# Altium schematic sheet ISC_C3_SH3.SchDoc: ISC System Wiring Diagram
size B; DrawnBy: Filiberto Clara; Engineer: Filiberto Clara; Organization: LIGO Laboratory; Address1: California Institute of Technology; Address2: Massachusetts Institute of Technology; SheetNumber: 7; SheetTotal: 39
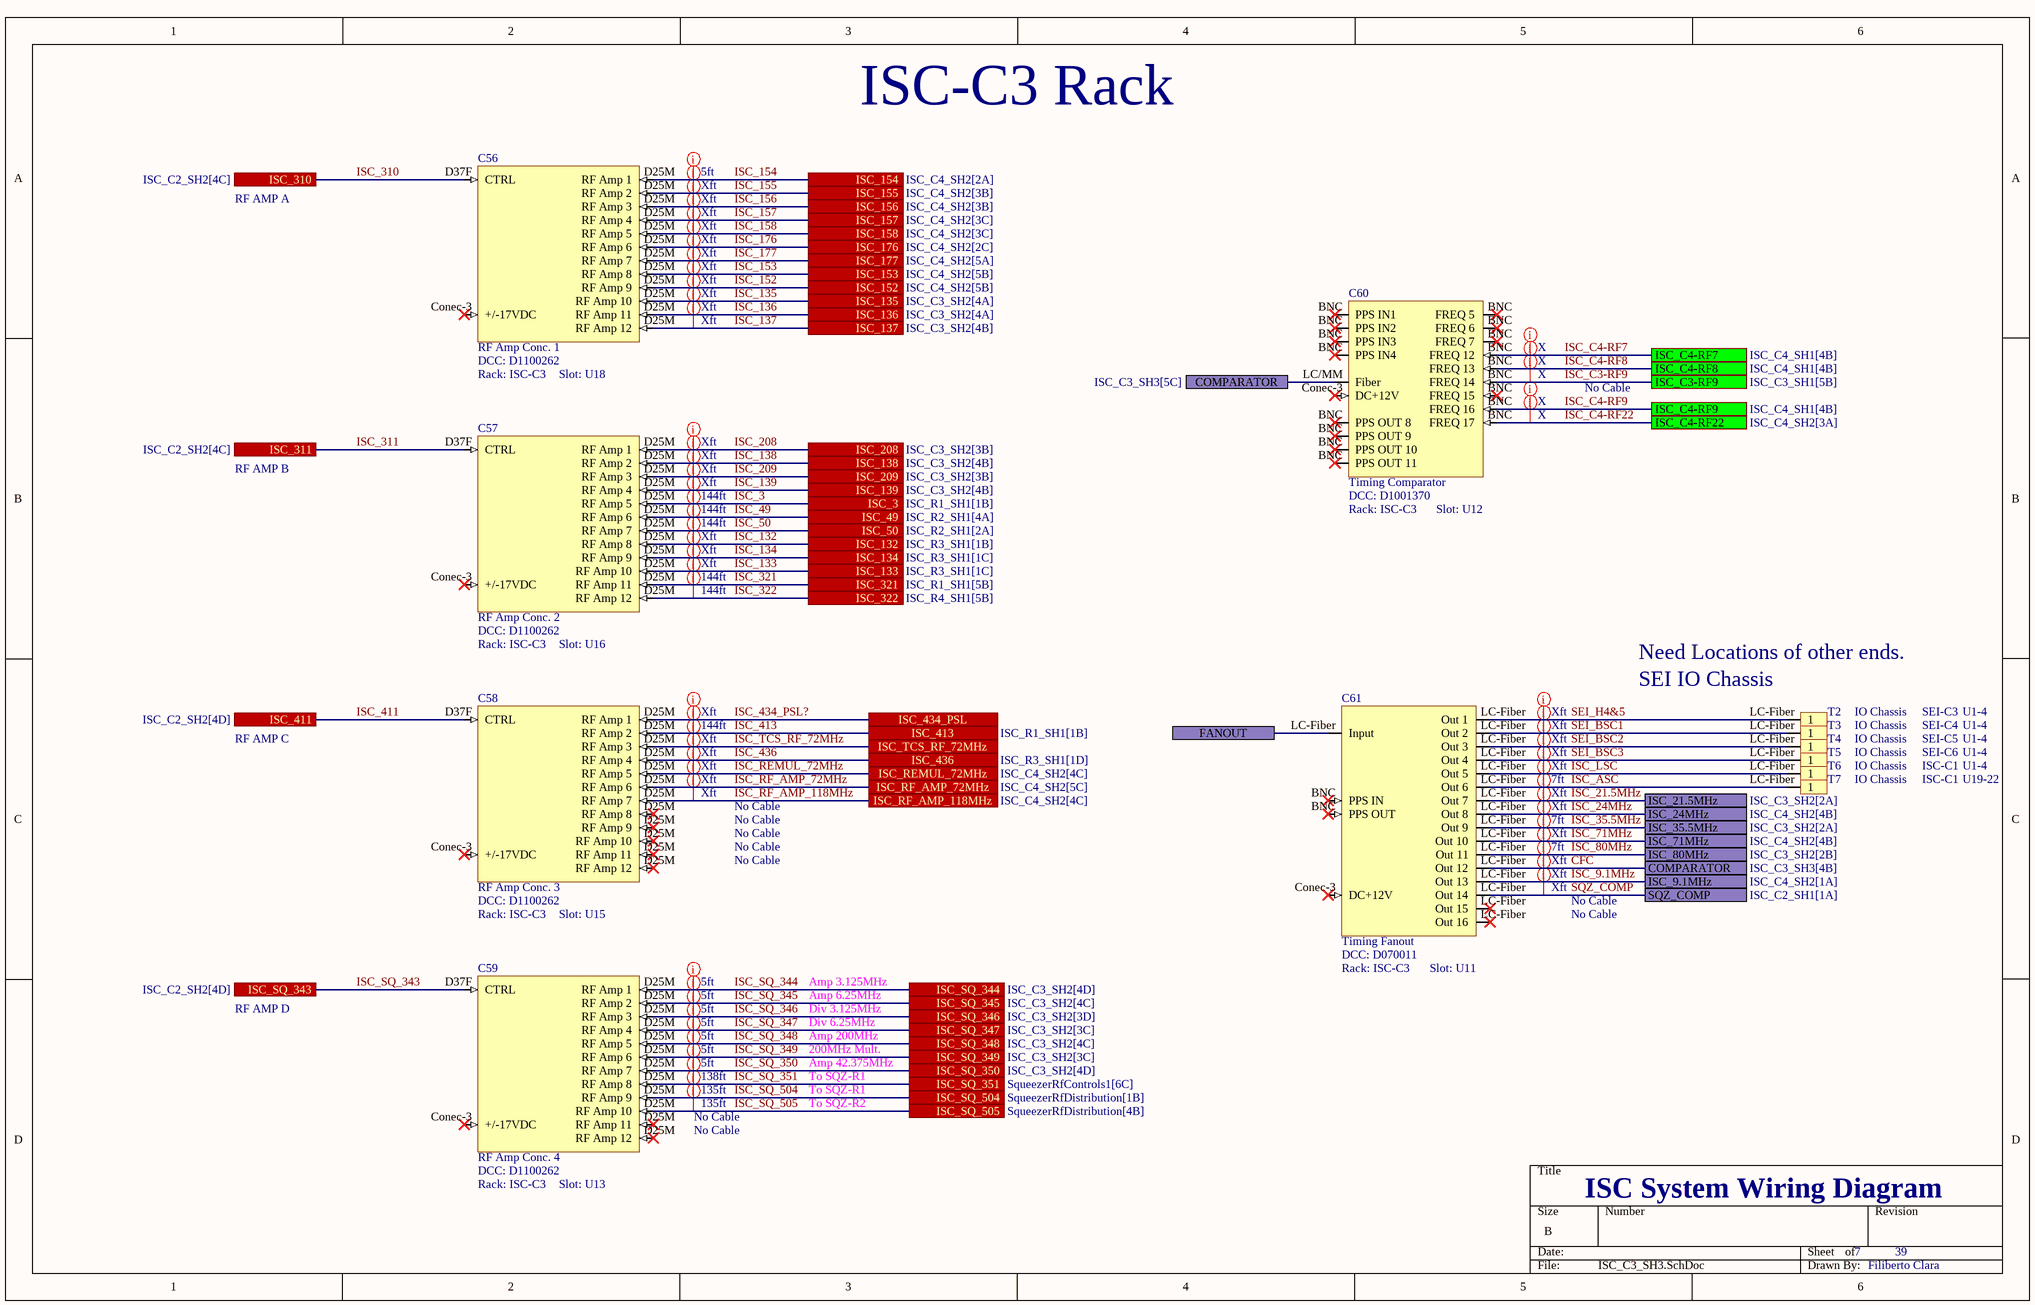
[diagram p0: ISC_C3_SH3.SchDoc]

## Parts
C56  RF Amp Conc. 1  DCC: D1100262  Rack: ISC-C3  Slot: U18
C57  RF Amp Conc. 2  DCC: D1100262  Rack: ISC-C3  Slot: U16
C58  RF Amp Conc. 3  DCC: D1100262  Rack: ISC-C3  Slot: U15
C59  RF Amp Conc. 4  DCC: D1100262  Rack: ISC-C3  Slot: U13
C60  Timing Comparator  DCC: D1001370  Rack: ISC-C3  Slot: U12
C61  Timing Fanout  DCC: D070011  Rack: ISC-C3  Slot: U11
T2  IO Chassis  Rack: SEI-C3  Slot: U1-4
T3  IO Chassis  Rack: SEI-C4  Slot: U1-4
T4  IO Chassis  Rack: SEI-C5  Slot: U1-4
T5  IO Chassis  Rack: SEI-C6  Slot: U1-4
T6  IO Chassis  Rack: ISC-C1  Slot: U1-4
T7  IO Chassis  Rack: ISC-C1  Slot: U19-22

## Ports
COMPARATOR (see ISC_C3_SH3[4B]), COMPARATOR (see ISC_C3_SH3[5C]), FANOUT, ISC_3 (see ISC_R1_SH1[1B]), ISC_9.1MHz (see ISC_C4_SH2[1A]), ISC_21.5MHz (see ISC_C3_SH2[2A]), ISC_24MHz (see ISC_C4_SH2[4B]), ISC_35.5MHz (see ISC_C3_SH2[2A]), ISC_49 (see ISC_R2_SH1[4A]), ISC_50 (see ISC_R2_SH1[2A]), ISC_71MHz (see ISC_C4_SH2[4B]), ISC_80MHz (see ISC_C3_SH2[2B]), ISC_132 (see ISC_R3_SH1[1B]), ISC_133 (see ISC_R3_SH1[1C]), ISC_134 (see ISC_R3_SH1[1C]), ISC_135 (see ISC_C3_SH2[4A]), ISC_136 (see ISC_C3_SH2[4A]), ISC_137 (see ISC_C3_SH2[4B]), ISC_138 (see ISC_C3_SH2[4B]), ISC_139 (see ISC_C3_SH2[4B]), ISC_152 (see ISC_C4_SH2[5B]), ISC_153 (see ISC_C4_SH2[5B]), ISC_154 (see ISC_C4_SH2[2A]), ISC_155 (see ISC_C4_SH2[3B]), ISC_156 (see ISC_C4_SH2[3B]), ISC_157 (see ISC_C4_SH2[3C]), ISC_158 (see ISC_C4_SH2[3C]), ISC_176 (see ISC_C4_SH2[2C]), ISC_177 (see ISC_C4_SH2[5A]), ISC_208 (see ISC_C3_SH2[3B]), ISC_209 (see ISC_C3_SH2[3B]), ISC_310 (see ISC_C2_SH2[4C]), ISC_311 (see ISC_C2_SH2[4C]), ISC_321 (see ISC_R1_SH1[5B]), ISC_322 (see ISC_R4_SH1[5B]), ISC_411 (see ISC_C2_SH2[4D]), ISC_413 (see ISC_R1_SH1[1B]), ISC_434_PSL, ISC_436 (see ISC_R3_SH1[1D]), ISC_C3-RF9 (see ISC_C3_SH1[5B]), ISC_C4-RF7 (see ISC_C4_SH1[4B]), ISC_C4-RF8 (see ISC_C4_SH1[4B]), ISC_C4-RF9 (see ISC_C4_SH1[4B]), ISC_C4-RF22 (see ISC_C4_SH2[3A]), ISC_REMUL_72MHz (see ISC_C4_SH2[4C]), ISC_RF_AMP_72MHz (see ISC_C4_SH2[5C]), ISC_RF_AMP_118MHz (see ISC_C4_SH2[4C]), ISC_SQ_343 (see ISC_C2_SH2[4D]), ISC_SQ_344 (see ISC_C3_SH2[4D]), ISC_SQ_345 (see ISC_C3_SH2[4C]), ISC_SQ_346 (see ISC_C3_SH2[3D]), ISC_SQ_347 (see ISC_C3_SH2[3C]), ISC_SQ_348 (see ISC_C3_SH2[4C]), ISC_SQ_349 (see ISC_C3_SH2[3C]), ISC_SQ_350 (see ISC_C3_SH2[4D]), ISC_SQ_351 (see SqueezerRfControls1[6C]), ISC_SQ_504 (see SqueezerRfDistribution[1B]), ISC_SQ_505 (see SqueezerRfDistribution[4B]), ISC_TCS_RF_72MHz, SQZ_COMP (see ISC_C2_SH1[1A])

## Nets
CFC: C60.LC/MM(Fiber) C61.LC-Fiber(Out_12) ; port COMPARATOR
FANOUT: C61.LC-Fiber(Input) ; port FANOUT
ISC_3: C57.D25M(RF_Amp_5) ; port ISC_3
ISC_9.1MHz: C61.LC-Fiber(Out_13) ; port ISC_9.1MHz
ISC_21.5MHz: C61.LC-Fiber(Out_7) ; port ISC_21.5MHz
ISC_24MHz: C61.LC-Fiber(Out_8) ; port ISC_24MHz
ISC_35.5MHz: C61.LC-Fiber(Out_9) ; port ISC_35.5MHz
ISC_49: C57.D25M(RF_Amp_6) ; port ISC_49
ISC_50: C57.D25M(RF_Amp_7) ; port ISC_50
ISC_71MHz: C61.LC-Fiber(Out_10) ; port ISC_71MHz
ISC_80MHz: C61.LC-Fiber(Out_11) ; port ISC_80MHz
ISC_132: C57.D25M(RF_Amp_8) ; port ISC_132
ISC_133: C57.D25M(RF_Amp_10) ; port ISC_133
ISC_134: C57.D25M(RF_Amp_9) ; port ISC_134
ISC_135: C56.D25M(RF_Amp_10) ; port ISC_135
ISC_136: C56.D25M(RF_Amp_11) ; port ISC_136
ISC_137: C56.D25M(RF_Amp_12) ; port ISC_137
ISC_138: C57.D25M(RF_Amp_2) ; port ISC_138
ISC_139: C57.D25M(RF_Amp_4) ; port ISC_139
ISC_152: C56.D25M(RF_Amp_9) ; port ISC_152
ISC_153: C56.D25M(RF_Amp_8) ; port ISC_153
ISC_154: C56.D25M(RF_Amp_1) ; port ISC_154
ISC_155: C56.D25M(RF_Amp_2) ; port ISC_155
ISC_156: C56.D25M(RF_Amp_3) ; port ISC_156
ISC_157: C56.D25M(RF_Amp_4) ; port ISC_157
ISC_158: C56.D25M(RF_Amp_5) ; port ISC_158
ISC_176: C56.D25M(RF_Amp_6) ; port ISC_176
ISC_177: C56.D25M(RF_Amp_7) ; port ISC_177
ISC_208: C57.D25M(RF_Amp_1) ; port ISC_208
ISC_209: C57.D25M(RF_Amp_3) ; port ISC_209
ISC_310: C56.D37F(CTRL) ; port ISC_310
ISC_311: C57.D37F(CTRL) ; port ISC_311
ISC_321: C57.D25M(RF_Amp_11) ; port ISC_321
ISC_322: C57.D25M(RF_Amp_12) ; port ISC_322
ISC_411: C58.D37F(CTRL) ; port ISC_411
ISC_413: C58.D25M(RF_Amp_2) ; port ISC_413
ISC_434_PSL?: C58.D25M(RF_Amp_1) ; port ISC_434_PSL
ISC_436: C58.D25M(RF_Amp_4) ; port ISC_436
ISC_ASC: C61.LC-Fiber(Out_6) T7.LC-Fiber(1)
ISC_C3-RF9: C60.BNC(FREQ_14) ; port ISC_C3-RF9
ISC_C4-RF7: C60.BNC(PPS_IN1) ; port ISC_C4-RF7
ISC_C4-RF8: C60.BNC(FREQ_13) ; port ISC_C4-RF8
ISC_C4-RF9: C60.BNC(FREQ_16) ; port ISC_C4-RF9
ISC_C4-RF22: C60.BNC(FREQ_17) ; port ISC_C4-RF22
ISC_LSC: C61.LC-Fiber(Out_5) T6.LC-Fiber(1)
ISC_REMUL_72MHz: C58.D25M(RF_Amp_5) ; port ISC_REMUL_72MHz
ISC_RF_AMP_72MHz: C58.D25M(RF_Amp_6) ; port ISC_RF_AMP_72MHz
ISC_RF_AMP_118MHz: C58.D25M(RF_Amp_7) ; port ISC_RF_AMP_118MHz
ISC_SQ_343: C59.D37F(CTRL) ; port ISC_SQ_343
ISC_SQ_344: C59.D25M(RF_Amp_1) ; port ISC_SQ_344
ISC_SQ_345: C59.D25M(RF_Amp_2) ; port ISC_SQ_345
ISC_SQ_346: C59.D25M(RF_Amp_3) ; port ISC_SQ_346
ISC_SQ_347: C59.D25M(RF_Amp_4) ; port ISC_SQ_347
ISC_SQ_348: C59.D25M(RF_Amp_5) ; port ISC_SQ_348
ISC_SQ_349: C59.D25M(RF_Amp_6) ; port ISC_SQ_349
ISC_SQ_350: C59.D25M(RF_Amp_7) ; port ISC_SQ_350
ISC_SQ_351: C59.D25M(RF_Amp_8) ; port ISC_SQ_351
ISC_SQ_504: C59.D25M(RF_Amp_9) ; port ISC_SQ_504
ISC_SQ_505: C59.D25M(RF_Amp_10) ; port ISC_SQ_505
ISC_TCS_RF_72MHz: C58.D25M(RF_Amp_3) ; port ISC_TCS_RF_72MHz
SEI_BSC1: C61.LC-Fiber(Out_2) T3.LC-Fiber(1)
SEI_BSC2: C61.LC-Fiber(Out_3) T4.LC-Fiber(1)
SEI_BSC3: C61.LC-Fiber(Out_4) T5.LC-Fiber(1)
SEI_H4&5: C61.LC-Fiber(Out_1) T2.LC-Fiber(1)
SQZ_COMP: C61.LC-Fiber(Out_14) ; port SQZ_COMP

Not connected (* = marked no-connect by the designer): C56 Conec-3(+/-17VDC)*; C57 Conec-3(+/-17VDC)*; C58 Conec-3(+/-17VDC)*; C59 Conec-3(+/-17VDC)*; C60 Conec-3(DC+12V)*; C61 BNC(PPS_IN)* Conec-3(DC+12V)*

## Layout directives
Length: 5ft: ISC_154, ISC_SQ_344, ISC_SQ_345, ISC_SQ_346, ISC_SQ_347, ISC_SQ_348, ISC_SQ_349, ISC_SQ_350
Length: 138ft: ISC_SQ_351
Length: Xft: CFC, ISC_9.1MHz, ISC_21.5MHz, ISC_24MHz, ISC_71MHz, ISC_132, ISC_133, ISC_134, ISC_135, ISC_136, ISC_137, ISC_138, ISC_139, ISC_152, ISC_153, ISC_155, ISC_156, ISC_157, ISC_158, ISC_176, ISC_177, ISC_208, ISC_209, ISC_434_PSL?, ISC_436, ISC_LSC, ISC_REMUL_72MHz, ISC_RF_AMP_72MHz, ISC_RF_AMP_118MHz, ISC_TCS_RF_72MHz, SEI_BSC1, SEI_BSC2, SEI_BSC3, SEI_H4&5, SQZ_COMP
Length: 144ft: ISC_3, ISC_49, ISC_50, ISC_321, ISC_322, ISC_413
Length: 7ft: ISC_35.5MHz, ISC_80MHz, ISC_ASC
Length: X: ISC_C3-RF9, ISC_C4-RF7, ISC_C4-RF8, ISC_C4-RF9, ISC_C4-RF22
Length: 135ft: ISC_SQ_504, ISC_SQ_505

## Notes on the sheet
- ISC-C3 Rack
- RF AMP A
- No Cable
- RF AMP B
- SEI IO Chassis
- Need Locations of other ends.
- RF AMP C
- Amp 3.125MHz
- RF AMP D
- Amp 6.25MHz
- Div 3.125MHz
- Div 6.25MHz
- Amp 200MHz
- 200MHz Mult.
- Amp 42.375MHz
- To SQZ-R1
- To SQZ-R2

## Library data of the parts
C56-C59 = RF Amp Conc.: Serial: Sxxxxxxx; System: ISC
C60 = Timing Comparator: Serial: Sxxxxxxx; System: ISC
C61 = Timing Fanout: Serial: Sxxxxxxx; System: ISC
T2-T7 = Placeholder: Serial: Sxxxxxxx; System: ISC; DCC: tbd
